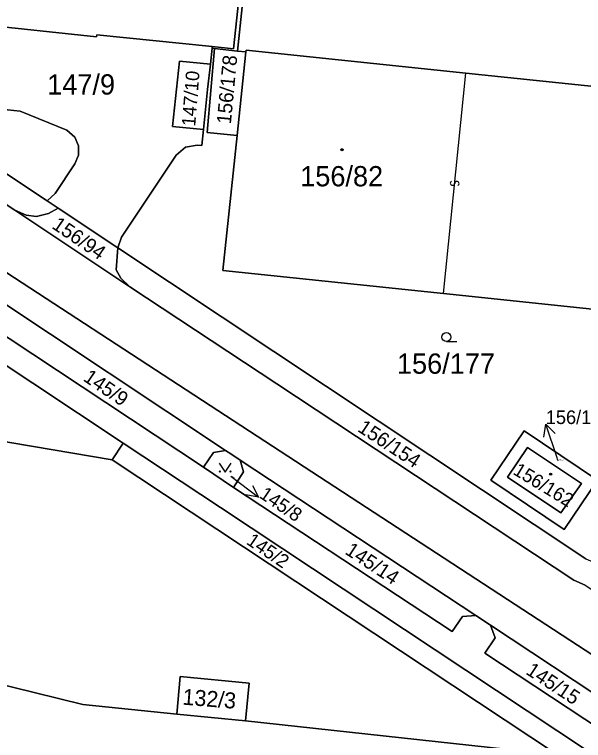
# Model space of a CAD drawing. Extents: x -598233 to -596890, y -1157848 to -1156431.
# Drawn here: x -597759 to -597711.3, y -1156881.8 to -1156820.9 of the extents above; entities that cross this region are included whole.
import ezdxf

# ---------------------------------------------------------------- set-up
doc = ezdxf.new("R2010")
doc.units = 0
for name, color, linetype in [('Level 1', 7, 'Continuous'), ('Level 13', 7, 'Continuous'), ('Level 3', 7, 'Continuous'), ('Level 4', 7, 'Continuous'), ('Level 5', 7, 'Continuous'), ('Level 57', 7, 'Continuous'), ('Level 60', 7, 'Continuous')]:
    doc.layers.add(name, color=color, linetype=linetype)

msp = doc.modelspace()

# ---------------------------------------------------------------- linework, layer by layer
at = {"layer": 'Level 1'}
for points in [[(-597768.59, -1156802.39), (-597768.42, -1156802.41), (-597767.74, -1156796.33), (-597761.55, -1156791.58), (-597737.44, -1156794.07), (-597740.62, -1156823.77), (-597742.4, -1156823.59)], [(-597737.42, -1156796.53), (-597740.29, -1156823.96)], [(-597758.96, -1156837.3), (-597779, -1156824.02), (-597781.84, -1156822.26), (-597784.16, -1156820.96), (-597785.42, -1156820.1), (-597786.53, -1156819.08), (-597787.7, -1156817.57), (-597788.47, -1156816.13), (-597788.99, -1156814.13), (-597789.04, -1156813.57)], [(-597797.68, -1156817.71), (-597707.2, -1156876.79)], [(-597756.23, -1156836.53), (-597780.11, -1156820.68)], [(-597742.4, -1156823.59), (-597752.08, -1156822.59), (-597752.1, -1156822.76), (-597762.12, -1156821.71)], [(-597742.2, -1156823.75), (-597742.83, -1156830.79), (-597740.32, -1156831.05)], [(-597742.56, -1156825.07), (-597742.42, -1156823.73)], [(-597742.4, -1156823.59), (-597742.42, -1156823.73)], [(-597742.2, -1156823.75), (-597742.42, -1156823.73)], [(-597740.29, -1156823.96), (-597742.2, -1156823.75)], [(-597740.29, -1156823.96), (-597739.59, -1156824.03)], [(-597739.59, -1156824.03), (-597739.57, -1156823.88), (-597721.14, -1156825.81)], [(-597739.59, -1156824.03), (-597740.32, -1156831.05)], [(-597743.14, -1156830.54), (-597745.73, -1156830.28), (-597745.16, -1156824.81), (-597742.56, -1156825.07)], [(-597743.14, -1156830.54), (-597742.79, -1156827.19), (-597742.56, -1156825.07)], [(-597721.14, -1156825.81), (-597704.74, -1156827.52)], [(-597762.24, -1156828.6), (-597758.51, -1156828.99), (-597754.58, -1156830.61), (-597753.92, -1156831.18), (-597753.61, -1156831.91), (-597753.61, -1156832.69), (-597753.91, -1156833.42), (-597755.56, -1156835.9), (-597756.23, -1156836.53)], [(-597743.14, -1156830.54), (-597743.28, -1156831.89), (-597743.66, -1156831.85), (-597744.65, -1156832.01), (-597745.44, -1156832.69), (-597750.01, -1156839.57), (-597750.32, -1156840.46)], [(-597740.32, -1156831.05), (-597741.51, -1156842.38), (-597723.03, -1156844.31)], [(-597756.23, -1156836.53), (-597755.31, -1156837.14)], [(-597758.96, -1156837.3), (-597757.99, -1156837.72), (-597757.12, -1156837.85), (-597756.13, -1156837.6), (-597755.31, -1156837.14)], [(-597749.3, -1156843.75), (-597758.96, -1156837.3)], [(-597755.31, -1156837.14), (-597750.32, -1156840.46)], [(-597749.3, -1156843.75), (-597750.07, -1156843.02), (-597750.45, -1156842.32), (-597750.32, -1156840.46)], [(-597750.32, -1156840.46), (-597711.08, -1156866.57), (-597709.77, -1156867.11), (-597708.96, -1156867.27), (-597707.73, -1156867.14), (-597706.87, -1156866.77), (-597706.12, -1156866.21), (-597705.6, -1156865.67), (-597702, -1156860.84)], [(-597711.15, -1156868.78), (-597712.09, -1156868.35), (-597736.98, -1156851.89), (-597749.3, -1156843.75)], [(-597760.9, -1156844.44), (-597741.3, -1156857.46)], [(-597723.03, -1156844.31), (-597710.53, -1156845.62)], [(-597765.04, -1156846.8), (-597749.87, -1156856.85)], [(-597743.14, -1156858.88), (-597761.52, -1156846.7)], [(-597784.63, -1156852.52), (-597750.8, -1156858.25)], [(-597716.25, -1156855.82), (-597719.04, -1156859.97), (-597712.9, -1156864.1), (-597710.11, -1156859.95), (-597716.25, -1156855.82)], [(-597749.87, -1156856.85), (-597750.8, -1156858.25)], [(-597710.87, -1156882.71), (-597741.72, -1156862.26), (-597749.87, -1156856.85)], [(-597741.3, -1156857.46), (-597742.29, -1156857.63), (-597743.14, -1156858.88)], [(-597741.3, -1156857.46), (-597740.76, -1156857.8), (-597740.07, -1156858.27)], [(-597715.97, -1156857.23), (-597711.46, -1156860.24), (-597713.17, -1156862.7), (-597717.65, -1156859.72), (-597715.97, -1156857.23)], [(-597750.8, -1156858.25), (-597713.45, -1156882.99)], [(-597740.61, -1156860.56), (-597739.79, -1156859.25), (-597740.07, -1156858.27)], [(-597740.07, -1156858.27), (-597720.31, -1156871.32)], [(-597743.14, -1156858.88), (-597740.61, -1156860.56)], [(-597720.31, -1156871.32), (-597721.43, -1156871.39), (-597722.28, -1156872.66), (-597740.61, -1156860.56)], [(-597719.09, -1156872.12), (-597720.31, -1156871.32)], [(-597709.78, -1156880.94), (-597719.56, -1156874.47), (-597718.7, -1156873.19), (-597719.09, -1156872.12)], [(-597719.09, -1156872.12), (-597708.61, -1156879.07)], [(-597775.55, -1156874.52), (-597767.22, -1156875.34), (-597753.25, -1156878.79), (-597745.38, -1156879.58)], [(-597745.38, -1156879.58), (-597745.09, -1156876.44), (-597739.3, -1156877), (-597739.61, -1156880.14)], [(-597739.61, -1156880.14), (-597745.38, -1156879.58)], [(-597739.61, -1156880.14), (-597713.45, -1156882.99)]]:
    msp.add_lwpolyline(points, dxfattribs=at)
at = {"layer": 'Level 13'}
for centre, start, end in [((-597722.263, -1156835.04), 121.53951, 353.63751), ((-597721.897, -1156835.08), 301.32506, 173.91506)]:
    msp.add_arc(centre, 0.184, start, end, dxfattribs=at)
at = {"layer": 'Level 3'}
msp.add_lwpolyline([(-597723.03, -1156844.31), (-597721.14, -1156825.81)], dxfattribs=at)
at = {"layer": 'Level 5'}
msp.add_line((-597722.77, -1156848.33), (-597721.895, -1156848.33), dxfattribs=at)
msp.add_lwpolyline([(-597741.821, -1156858.53), (-597741.32, -1156859.28), (-597740.82, -1156858.53)], dxfattribs=at)
for centre, radius in [((-597731.53, -1156832.24), 0.09), ((-597731.53, -1156832.24), 0.0521), ((-597722.77, -1156847.955), 0.375), ((-597741.77, -1156859.23), 0.05), ((-597740.871, -1156859.23), 0.05), ((-597714.04, -1156859.46), 0.09), ((-597714.04, -1156859.46), 0.0521)]:
    msp.add_circle(centre, radius, dxfattribs=at)
at = {"layer": 'Level 57'}
for p, q in [((-597713.492, -1156858.095), (-597714.445, -1156855.25)), ((-597713.42, -1156858.31), (-597713.492, -1156858.095)), ((-597740.85, -1156859.63), (-597738.536, -1156861.371))]:
    msp.add_line(p, q, dxfattribs=at)
for points in [[(-597714.601, -1156856.357), (-597714.445, -1156855.25), (-597713.653, -1156856.04)], [(-597739.017, -1156860.405), (-597738.536, -1156861.371), (-597739.598, -1156861.177)]]:
    msp.add_lwpolyline(points, dxfattribs=at)
at = {"layer": 'Level 60'}
for points in [[(-597768.59, -1156802.39), (-597768.42, -1156802.41), (-597767.74, -1156796.33), (-597761.55, -1156791.58), (-597737.44, -1156794.07), (-597740.62, -1156823.77), (-597742.4, -1156823.59), (-597752.08, -1156822.59), (-597752.1, -1156822.76), (-597762.12, -1156821.71), (-597767.49, -1156821.15), (-597770.56, -1156820.83), (-597769.4, -1156809.95)], [(-597758.96, -1156837.3), (-597749.3, -1156843.75), (-597736.98, -1156851.89), (-597712.09, -1156868.35), (-597711.15, -1156868.78), (-597704.79, -1156872.9), (-597707.2, -1156876.79), (-597797.68, -1156817.71), (-597789.04, -1156813.57), (-597788.99, -1156814.13), (-597788.47, -1156816.13), (-597787.7, -1156817.57), (-597786.53, -1156819.08), (-597785.42, -1156820.1), (-597784.16, -1156820.96), (-597781.84, -1156822.26), (-597779, -1156824.02)], [(-597757.99, -1156837.72), (-597758.96, -1156837.3), (-597779, -1156824.02), (-597781.84, -1156822.26), (-597784.16, -1156820.96), (-597785.42, -1156820.1), (-597786.53, -1156819.08), (-597787.7, -1156817.57), (-597788.47, -1156816.13), (-597788.99, -1156814.13), (-597789.04, -1156813.57), (-597786.44, -1156815.08), (-597785.23, -1156817.2), (-597783.34, -1156818.75), (-597780.11, -1156820.68), (-597756.23, -1156836.53), (-597755.31, -1156837.14), (-597756.13, -1156837.6), (-597757.12, -1156837.85)], [(-597794.07, -1156823.89), (-597799.58, -1156821.48), (-597801.05, -1156820.96), (-597797.68, -1156817.71), (-597707.2, -1156876.79), (-597708.61, -1156879.07), (-597719.09, -1156872.12), (-597720.31, -1156871.32), (-597740.07, -1156858.27), (-597740.76, -1156857.8), (-597741.3, -1156857.46), (-597760.9, -1156844.44), (-597762.14, -1156843.6), (-597782.73, -1156829.95), (-597788.59, -1156826.54)], [(-597740.29, -1156823.96), (-597739.59, -1156824.03), (-597740.32, -1156831.05), (-597742.83, -1156830.79), (-597742.2, -1156823.75)], [(-597739.59, -1156824.03), (-597739.57, -1156823.88), (-597721.14, -1156825.81), (-597704.74, -1156827.52), (-597699.2, -1156828.1), (-597690.24, -1156829.04), (-597692.18, -1156847.54), (-597705.04, -1156846.19), (-597710.53, -1156845.62), (-597723.03, -1156844.31), (-597741.51, -1156842.38), (-597740.32, -1156831.05)], [(-597745.73, -1156830.28), (-597745.16, -1156824.81), (-597742.56, -1156825.07), (-597742.79, -1156827.19), (-597743.14, -1156830.54)], [(-597749.3, -1156843.75), (-597758.96, -1156837.3), (-597757.99, -1156837.72), (-597757.12, -1156837.85), (-597756.13, -1156837.6), (-597755.31, -1156837.14), (-597750.32, -1156840.46), (-597750.45, -1156842.32), (-597750.07, -1156843.02)], [(-597761.52, -1156846.7), (-597760.67, -1156845.43), (-597760.9, -1156844.44), (-597741.3, -1156857.46), (-597742.29, -1156857.63), (-597743.14, -1156858.88)], [(-597719.04, -1156859.97), (-597716.25, -1156855.82), (-597710.11, -1156859.95), (-597712.9, -1156864.1)], [(-597716.25, -1156855.82), (-597719.04, -1156859.97), (-597712.9, -1156864.1), (-597710.11, -1156859.95)], [(-597741.72, -1156862.26), (-597710.87, -1156882.71), (-597711.75, -1156884.12), (-597713.45, -1156882.99), (-597750.8, -1156858.25), (-597749.87, -1156856.85)], [(-597742.29, -1156857.63), (-597741.3, -1156857.46), (-597740.76, -1156857.8), (-597740.07, -1156858.27), (-597739.79, -1156859.25), (-597740.61, -1156860.56), (-597743.14, -1156858.88)], [(-597715.97, -1156857.23), (-597711.46, -1156860.24), (-597713.17, -1156862.7), (-597717.65, -1156859.72)], [(-597711.46, -1156860.24), (-597715.97, -1156857.23), (-597717.65, -1156859.72), (-597713.17, -1156862.7)], [(-597720.31, -1156871.32), (-597721.43, -1156871.39), (-597722.28, -1156872.66), (-597740.61, -1156860.56), (-597739.79, -1156859.25), (-597740.07, -1156858.27)], [(-597709.78, -1156880.94), (-597719.56, -1156874.47), (-597718.7, -1156873.19), (-597719.09, -1156872.12), (-597708.61, -1156879.07)], [(-597745.38, -1156879.58), (-597745.09, -1156876.44), (-597739.3, -1156877), (-597739.61, -1156880.14)]]:
    msp.add_lwpolyline(points, close=True, dxfattribs=at)
for points in [[(-597737.42, -1156796.53), (-597740.29, -1156823.96), (-597742.2, -1156823.75), (-597742.42, -1156823.73), (-597742.4, -1156823.59), (-597740.62, -1156823.77), (-597737.44, -1156794.07)], [(-597704.74, -1156827.52), (-597721.14, -1156825.81), (-597739.57, -1156823.88), (-597739.59, -1156824.03), (-597740.29, -1156823.96), (-597737.42, -1156796.53), (-597732.51, -1156797.05), (-597720.33, -1156798.33), (-597719.92, -1156794.4), (-597714.54, -1156794.96), (-597715.34, -1156802.54), (-597716.47, -1156813.31), (-597712.55, -1156813.77), (-597694.05, -1156815.71)], [(-597770.56, -1156820.83), (-597767.49, -1156821.15), (-597767.79, -1156823.99), (-597768.03, -1156826.33), (-597765.23, -1156828.28), (-597762.24, -1156828.6), (-597758.51, -1156828.99), (-597754.58, -1156830.61), (-597753.92, -1156831.18), (-597753.61, -1156831.91), (-597753.61, -1156832.69), (-597753.91, -1156833.42), (-597755.56, -1156835.9), (-597756.23, -1156836.53), (-597780.11, -1156820.68)], [(-597762.12, -1156821.71), (-597752.1, -1156822.76), (-597752.08, -1156822.59), (-597742.4, -1156823.59), (-597742.42, -1156823.73), (-597742.56, -1156825.07), (-597745.16, -1156824.81), (-597745.73, -1156830.28), (-597743.14, -1156830.54), (-597743.28, -1156831.89), (-597743.66, -1156831.85), (-597744.65, -1156832.01), (-597745.44, -1156832.69), (-597750.01, -1156839.57), (-597750.32, -1156840.46), (-597755.31, -1156837.14), (-597756.23, -1156836.53), (-597755.56, -1156835.9), (-597753.91, -1156833.42), (-597753.61, -1156832.69), (-597753.61, -1156831.91), (-597753.92, -1156831.18), (-597754.58, -1156830.61), (-597758.51, -1156828.99), (-597762.24, -1156828.6)], [(-597711.08, -1156866.57), (-597750.32, -1156840.46), (-597750.01, -1156839.57), (-597745.44, -1156832.69), (-597744.65, -1156832.01), (-597743.66, -1156831.85), (-597743.28, -1156831.89), (-597743.14, -1156830.54), (-597742.79, -1156827.19), (-597742.56, -1156825.07), (-597742.42, -1156823.73), (-597742.2, -1156823.75), (-597742.83, -1156830.79), (-597740.32, -1156831.05), (-597741.51, -1156842.38), (-597723.03, -1156844.31), (-597710.53, -1156845.62)], [(-597711.15, -1156868.78), (-597712.09, -1156868.35), (-597736.98, -1156851.89), (-597749.3, -1156843.75), (-597750.07, -1156843.02), (-597750.45, -1156842.32), (-597750.32, -1156840.46), (-597711.08, -1156866.57)], [(-597765.04, -1156846.8), (-597749.87, -1156856.85), (-597750.8, -1156858.25), (-597784.63, -1156852.52)], [(-597710.87, -1156882.71), (-597741.72, -1156862.26), (-597749.87, -1156856.85), (-597765.04, -1156846.8)], [(-597761.52, -1156846.7), (-597743.14, -1156858.88), (-597740.61, -1156860.56), (-597722.28, -1156872.66), (-597721.43, -1156871.39), (-597720.31, -1156871.32), (-597719.09, -1156872.12), (-597718.7, -1156873.19), (-597719.56, -1156874.47), (-597709.78, -1156880.94)], [(-597814.83, -1156847.4), (-597793.39, -1156851.03), (-597784.63, -1156852.52), (-597750.8, -1156858.25), (-597713.45, -1156882.99), (-597739.61, -1156880.14), (-597739.3, -1156877), (-597745.09, -1156876.44), (-597745.38, -1156879.58), (-597753.25, -1156878.79), (-597767.22, -1156875.34), (-597775.55, -1156874.52), (-597775.27, -1156871.46), (-597775.05, -1156871.48), (-597773.88, -1156859.59), (-597801.24, -1156856.91), (-597801.27, -1156857.19), (-597802.88, -1156857.04)], [(-597760.34, -1156882.38), (-597795.04, -1156878.86), (-597797.99, -1156878.23), (-597800.76, -1156877.09), (-597803.62, -1156876.12), (-597804.58, -1156875.91), (-597809.58, -1156875.41), (-597812.57, -1156875.58), (-597814.51, -1156876.06), (-597816.45, -1156876.61), (-597817.47, -1156876.55), (-597829.19, -1156875.22), (-597828.79, -1156871.71), (-597828.52, -1156869.3), (-597826.13, -1156869.54), (-597810.63, -1156871.06), (-597804.3, -1156871.68), (-597802.76, -1156871.84), (-597775.55, -1156874.52), (-597767.22, -1156875.34), (-597753.25, -1156878.79), (-597745.38, -1156879.58), (-597739.61, -1156880.14), (-597713.45, -1156882.99)]]:
    msp.add_lwpolyline(points, dxfattribs=at)

# ---------------------------------------------------------------- texts
at = {"layer": 'Level 4'}
for s, height, rotation, p in [('156/178', 1.2, 84.6, (-597740.843, -1156830.131)), ('147/10', 1.14, 85.42611, (-597743.83, -1156830.31)), ('156/94', 1.2, 325.8, (-597755.921, -1156838.771)), ('145/9', 1.2, 325.8, (-597753.295, -1156851.562)), ('156/154', 1.2, 326.7, (-597730.294, -1156855.809)), ('156/162', 1.14, 328.69584, (-597717.269, -1156859.405)), ('145/8', 0.1, 325.93383, (-597740.85, -1156859.63)), ('145/2', 1.14, 325.73889, (-597739.62, -1156865.26)), ('145/14', 1.2, 326.7, (-597731.35, -1156866.091)), ('145/15', 1.2, 326.7, (-597716.195, -1156876.165)), ('132/3', 1.34, 355.5, (-597744.929, -1156878.786))]:
    msp.add_text(s, height=height, rotation=rotation, dxfattribs=at).set_placement(p)
for s, height, p in [('147/9', 1.7, (-597756.237, -1156827.61)), ('156/82', 1.7, (-597735.03, -1156835.31)), ('156/177', 1.7, (-597726.922, -1156851.03)), ('156/147', 0.1, (-597713.42, -1156858.31))]:
    msp.add_text(s, height=height, dxfattribs=at).set_placement(p)
at = {"layer": 'Level 57'}
msp.add_text('156/147', height=1.14, dxfattribs=at).set_placement((-597714.445, -1156855.25))
msp.add_text('145/8', height=1.14, rotation=325.93383, dxfattribs=at).set_placement((-597738.536, -1156861.371))

doc.saveas('drawing.dxf')
